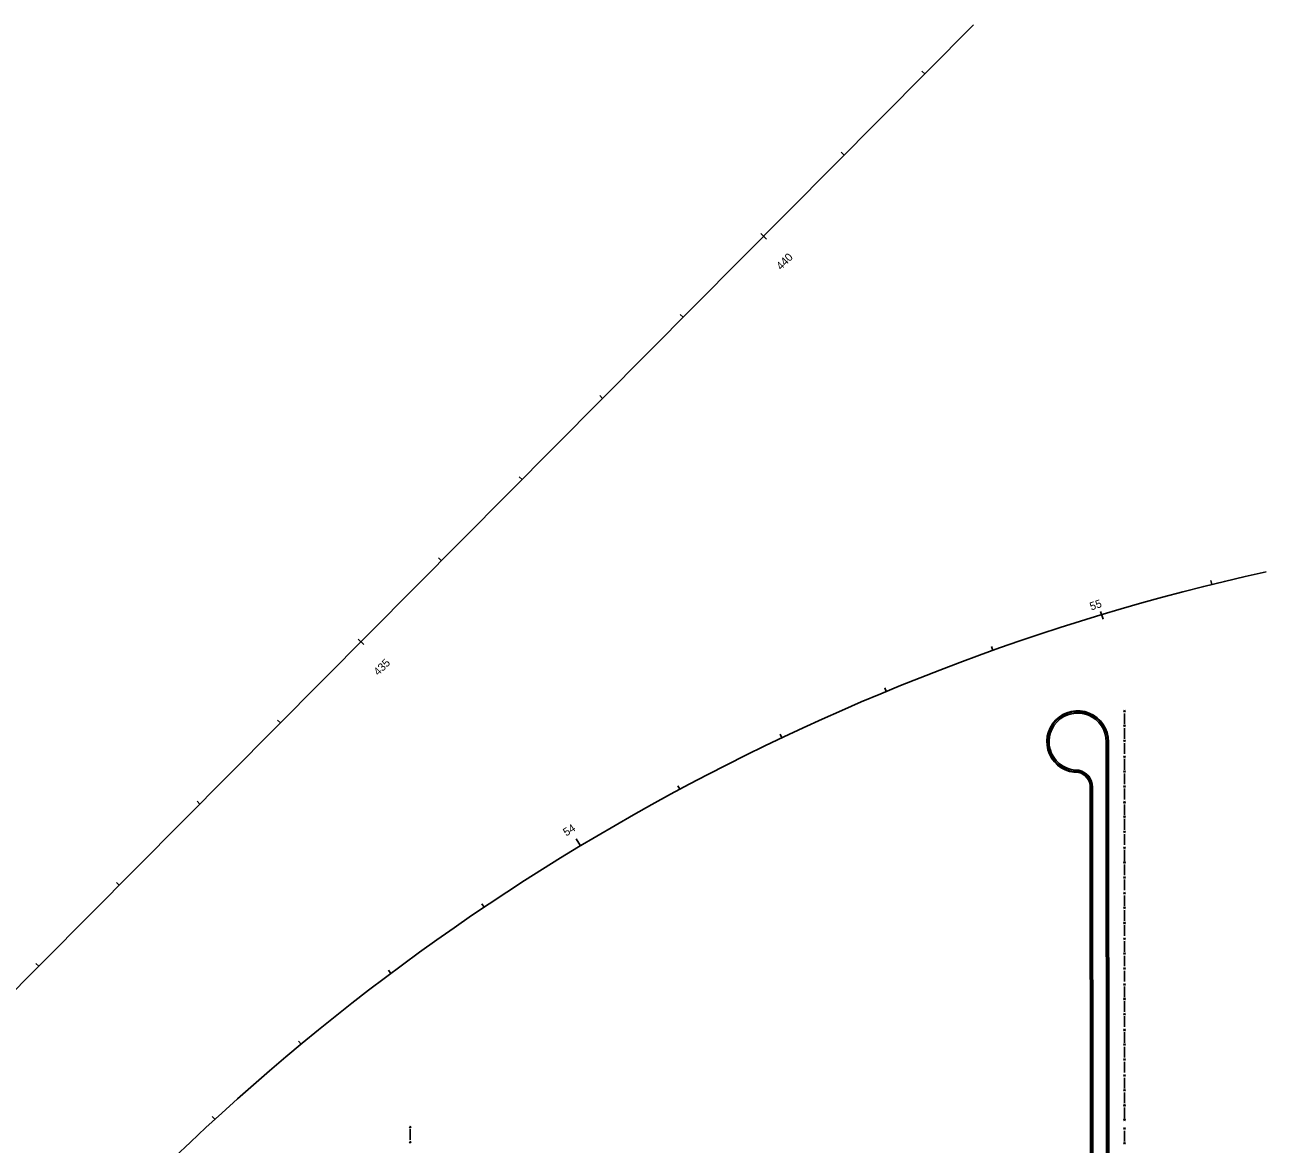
# Model space of a CAD drawing. Extents: x 6711323 to 6714641, y 1869258 to 1871224.
# Drawn here: x 6712223 to 6713309, y 1870245 to 1871224 of the extents above; entities that cross this region are included whole.
import ezdxf

# ---------------------------------------------------------------- set-up
doc = ezdxf.new("R2010")
doc.units = 0
for name, color, linetype in [('Exist Man Md (2)', 7, 'Continuous'), ('Level 11', 7, 'Continuous'), ('Level 13', 7, 'Continuous'), ('Level 14', 7, 'Continuous'), ('Level 15', 7, 'Continuous'), ('Level 16', 7, 'Continuous'), ('Level 60', 7, 'Continuous'), ('Nongeo Data(60)', 7, 'Continuous'), ('Sheet Format(10)', 7, 'Continuous')]:
    doc.layers.add(name, color=color, linetype=linetype)

msp = doc.modelspace()

# ---------------------------------------------------------------- linework, layer by layer
at = {"layer": 'Exist Man Md (2)'}
for p, q in [((6713184.3, 1870624.3), (6713185.8, 1870623.1)), ((6713185.8, 1870624.3), (6713184.3, 1870623.1)), ((6713185, 1870612.5), (6713185, 1870621.8)), ((6713184.3, 1870611.6), (6713185.8, 1870610.3)), ((6713185.8, 1870611.6), (6713184.3, 1870610.3)), ((6713185, 1870599.7), (6713185, 1870609)), ((6713184.3, 1870598.4), (6713185.8, 1870597.2)), ((6713185.8, 1870598.4), (6713184.3, 1870597.2)), ((6713185, 1870586.5), (6713185, 1870595.8)), ((6713184.3, 1870584.5), (6713185.8, 1870583.3)), ((6713185.8, 1870584.5), (6713184.3, 1870583.3)), ((6713184.3, 1870544.8), (6713185.8, 1870543.6)), ((6713185.8, 1870544.8), (6713184.3, 1870543.6)), ((6713185, 1870532.9), (6713185, 1870542.2)), ((6713184.3, 1870532), (6713185.8, 1870530.8)), ((6713185.8, 1870532), (6713184.3, 1870530.8)), ((6713185, 1870520.1), (6713185, 1870529.5)), ((6713184.3, 1870518.8), (6713185.8, 1870517.6)), ((6713185.8, 1870518.8), (6713184.3, 1870517.6)), ((6713185, 1870506.9), (6713185, 1870516.3)), ((6713184.3, 1870504.9), (6713185.8, 1870503.7)), ((6713185.8, 1870504.9), (6713184.3, 1870503.7)), ((6713184.3, 1870259.2), (6713185.8, 1870258)), ((6713185.8, 1870259.2), (6713184.3, 1870258)), ((6713185, 1870247.3), (6713185, 1870256.7)), ((6713184.3, 1870246.4), (6713185.8, 1870245.2)), ((6713185.8, 1870246.4), (6713184.3, 1870245.2))]:
    msp.add_line(p, q, dxfattribs=at)
at = {"layer": 'Level 11'}
for p, q in [((6713010.3, 1871181.2), (6713007.8, 1871183.6)), ((6712939.8, 1871110.2), (6712937.3, 1871112.7)), ((6712866.9, 1871041.7), (6712871.8, 1871036.8)), ((6712798.9, 1870968.3), (6712796.4, 1870970.8)), ((6712728.4, 1870897.3), (6712726, 1870899.8)), ((6712658, 1870826.4), (6712655.5, 1870828.8)), ((6712587.5, 1870755.4), (6712585, 1870757.9)), ((6712514.6, 1870686.9), (6712519.6, 1870682)), ((6712446.6, 1870613.5), (6712444.1, 1870615.9)), ((6712376.2, 1870542.5), (6712373.7, 1870545)), ((6712305.7, 1870471.5), (6712303.2, 1870474)), ((6712235.2, 1870400.6), (6712232.8, 1870403))]:
    msp.add_line(p, q, dxfattribs=at)
at = {"layer": 'Level 13'}
msp.add_arc((6713741.5, 1868793.1), 2000, 102.4898, 136.59, dxfattribs=at)
at = {"layer": 'Level 14'}
for p, q in [((6713261.5, 1870734.6), (6713260.6, 1870738)), ((6713164.2, 1870710.9), (6713166.3, 1870704.2)), ((6713070, 1870677), (6713068.8, 1870680.3)), ((6712976.7, 1870641.1), (6712975.4, 1870644.3)), ((6712885.3, 1870600.5), (6712883.8, 1870603.7)), ((6712796, 1870555.5), (6712794.4, 1870558.6)), ((6712705.5, 1870512), (6712709.1, 1870506)), ((6712624.8, 1870452.3), (6712622.9, 1870455.2)), ((6712543.3, 1870394.4), (6712541.2, 1870397.2)), ((6712464.8, 1870332.5), (6712462.5, 1870335.2)), ((6712389.4, 1870266.8), (6712387, 1870269.3))]:
    msp.add_line(p, q, dxfattribs=at)
at = {"layer": 'Level 15'}
msp.add_line((6711851.4, 1870014), (6713052.9, 1871224.2), dxfattribs=at)
at = {"layer": 'Level 60'}
for p, q in [((6712560.9, 1870260.5), (6712559.4, 1870259.3)), ((6712559.5, 1870260.5), (6712561, 1870259.3)), ((6712560.2, 1870248.7), (6712560.2, 1870258)), ((6712560.9, 1870247.4), (6712559.4, 1870246.1)), ((6712559.5, 1870247.4), (6712561, 1870246.1))]:
    msp.add_line(p, q, dxfattribs=at)
at = {"layer": 'Nongeo Data(60)'}
for p, q in [((6713185, 1870572.6), (6713185, 1870582)), ((6713184.3, 1870571.7), (6713185.8, 1870570.5)), ((6713185.8, 1870571.7), (6713184.3, 1870570.5)), ((6713185, 1870559.8), (6713185, 1870569.2)), ((6713184.3, 1870558.5), (6713185.8, 1870557.3)), ((6713185.8, 1870558.5), (6713184.3, 1870557.3)), ((6713185, 1870546.6), (6713185, 1870556)), ((6713184.3, 1870544.7), (6713185.8, 1870543.4)), ((6713185.8, 1870544.7), (6713184.3, 1870543.4)), ((6713185, 1870493), (6713185, 1870502.4)), ((6713184.3, 1870492.2), (6713185.8, 1870490.9)), ((6713185.8, 1870492.2), (6713184.3, 1870490.9)), ((6713185, 1870480.3), (6713185, 1870489.6)), ((6713184.3, 1870479), (6713185.8, 1870477.7)), ((6713185.8, 1870479), (6713184.3, 1870477.7)), ((6713185, 1870467.1), (6713185, 1870476.4)), ((6713184.3, 1870465.1), (6713185.8, 1870463.9)), ((6713185.8, 1870465.1), (6713184.3, 1870463.9)), ((6713185, 1870453.2), (6713185, 1870462.6)), ((6713184.3, 1870452.3), (6713185.8, 1870451.1)), ((6713185.8, 1870452.3), (6713184.3, 1870451.1)), ((6713185, 1870440.4), (6713185, 1870449.8)), ((6713184.3, 1870439.1), (6713185.8, 1870437.9)), ((6713185.8, 1870439.1), (6713184.3, 1870437.9)), ((6713185, 1870427.2), (6713185, 1870436.6)), ((6713184.3, 1870425.3), (6713185.8, 1870424)), ((6713185.8, 1870425.3), (6713184.3, 1870424)), ((6713185, 1870413.4), (6713185, 1870422.7)), ((6713184.3, 1870412.5), (6713185.8, 1870411.2)), ((6713185.8, 1870412.5), (6713184.3, 1870411.2)), ((6713185, 1870400.6), (6713185, 1870409.9)), ((6713184.3, 1870399.3), (6713185.8, 1870398.1)), ((6713185.8, 1870399.3), (6713184.3, 1870398.1)), ((6713185, 1870387.4), (6713185, 1870396.7)), ((6713184.3, 1870385.4), (6713185.8, 1870384.2)), ((6713185.8, 1870385.4), (6713184.3, 1870384.2)), ((6713185, 1870373.5), (6713185, 1870382.9)), ((6713184.3, 1870372.6), (6713185.8, 1870371.4)), ((6713185.8, 1870372.6), (6713184.3, 1870371.4)), ((6713185, 1870360.7), (6713185, 1870370.1)), ((6713184.3, 1870359.4), (6713185.8, 1870358.2)), ((6713185.8, 1870359.4), (6713184.3, 1870358.2)), ((6713185, 1870347.6), (6713185, 1870356.9)), ((6713184.3, 1870345.6), (6713185.8, 1870344.3)), ((6713185.8, 1870345.6), (6713184.3, 1870344.3)), ((6713185, 1870333.7), (6713185, 1870343)), ((6713184.3, 1870332.8), (6713185.8, 1870331.6)), ((6713185.8, 1870332.8), (6713184.3, 1870331.6)), ((6713185, 1870320.9), (6713185, 1870330.2)), ((6713184.3, 1870319.6), (6713185.8, 1870318.4)), ((6713185.8, 1870319.6), (6713184.3, 1870318.4)), ((6713185, 1870307.7), (6713185, 1870317.1)), ((6713184.3, 1870305.6), (6713185.8, 1870304.4)), ((6713185.8, 1870305.6), (6713184.3, 1870304.4)), ((6713185, 1870293.7), (6713185, 1870303)), ((6713184.3, 1870292.8), (6713185.8, 1870291.6)), ((6713185.8, 1870292.8), (6713184.3, 1870291.6)), ((6713185, 1870280.9), (6713185, 1870290.3)), ((6713184.3, 1870279.6), (6713185.8, 1870278.4)), ((6713185.8, 1870279.6), (6713184.3, 1870278.4)), ((6713185, 1870267.7), (6713185, 1870277.1)), ((6713184.3, 1870267.1), (6713185.8, 1870265.8)), ((6713185.8, 1870267.1), (6713184.3, 1870265.8))]:
    msp.add_line(p, q, dxfattribs=at)
at = {"layer": 'Sheet Format(10)'}
for p, q in [((6713169.3, 1870072.1), (6713169.1, 1870597.1)), ((6713170.6, 1870072.1), (6713170.5, 1870597.1)), ((6713171.3, 1870072.1), (6713171.1, 1870597.1)), ((6713155.1, 1870557.5), (6713155.3, 1870111.6)), ((6713155.8, 1870557.5), (6713156, 1870111.6)), ((6713157.1, 1870557.5), (6713157.3, 1870111.6))]:
    msp.add_line(p, q, dxfattribs=at)
for centre, radius, start, end in [((6713144.1, 1870597.1), 27, 0, 271.738), ((6713144.1, 1870597.1), 26.3, 0, 271.9153), ((6713144.1, 1870597.1), 25, 0, 272.2775), ((6713142.1, 1870557.4), 13.7, 0.0192, 77.8909), ((6713142.1, 1870557.4), 13, 0.0192, 77.5362), ((6713142.1, 1870557.4), 15, 0.0192, 78.5399)]:
    msp.add_arc(centre, radius, start, end, dxfattribs=at)

# ---------------------------------------------------------------- texts
at = {"layer": 'Level 16'}
for s, rotation, p in [('440', 45.2058, (6712884.6, 1871009.2)), ('55', 18.8064, (6713156, 1870711.8)), ('435', 45.2058, (6712532.3, 1870654.4)), ('54', 32.6725, (6712696.7, 1870514.1))]:
    msp.add_text(s, height=7, rotation=rotation, dxfattribs=at).set_placement(p)

doc.saveas('drawing.dxf')
